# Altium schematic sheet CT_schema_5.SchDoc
size 278 x 236 mm
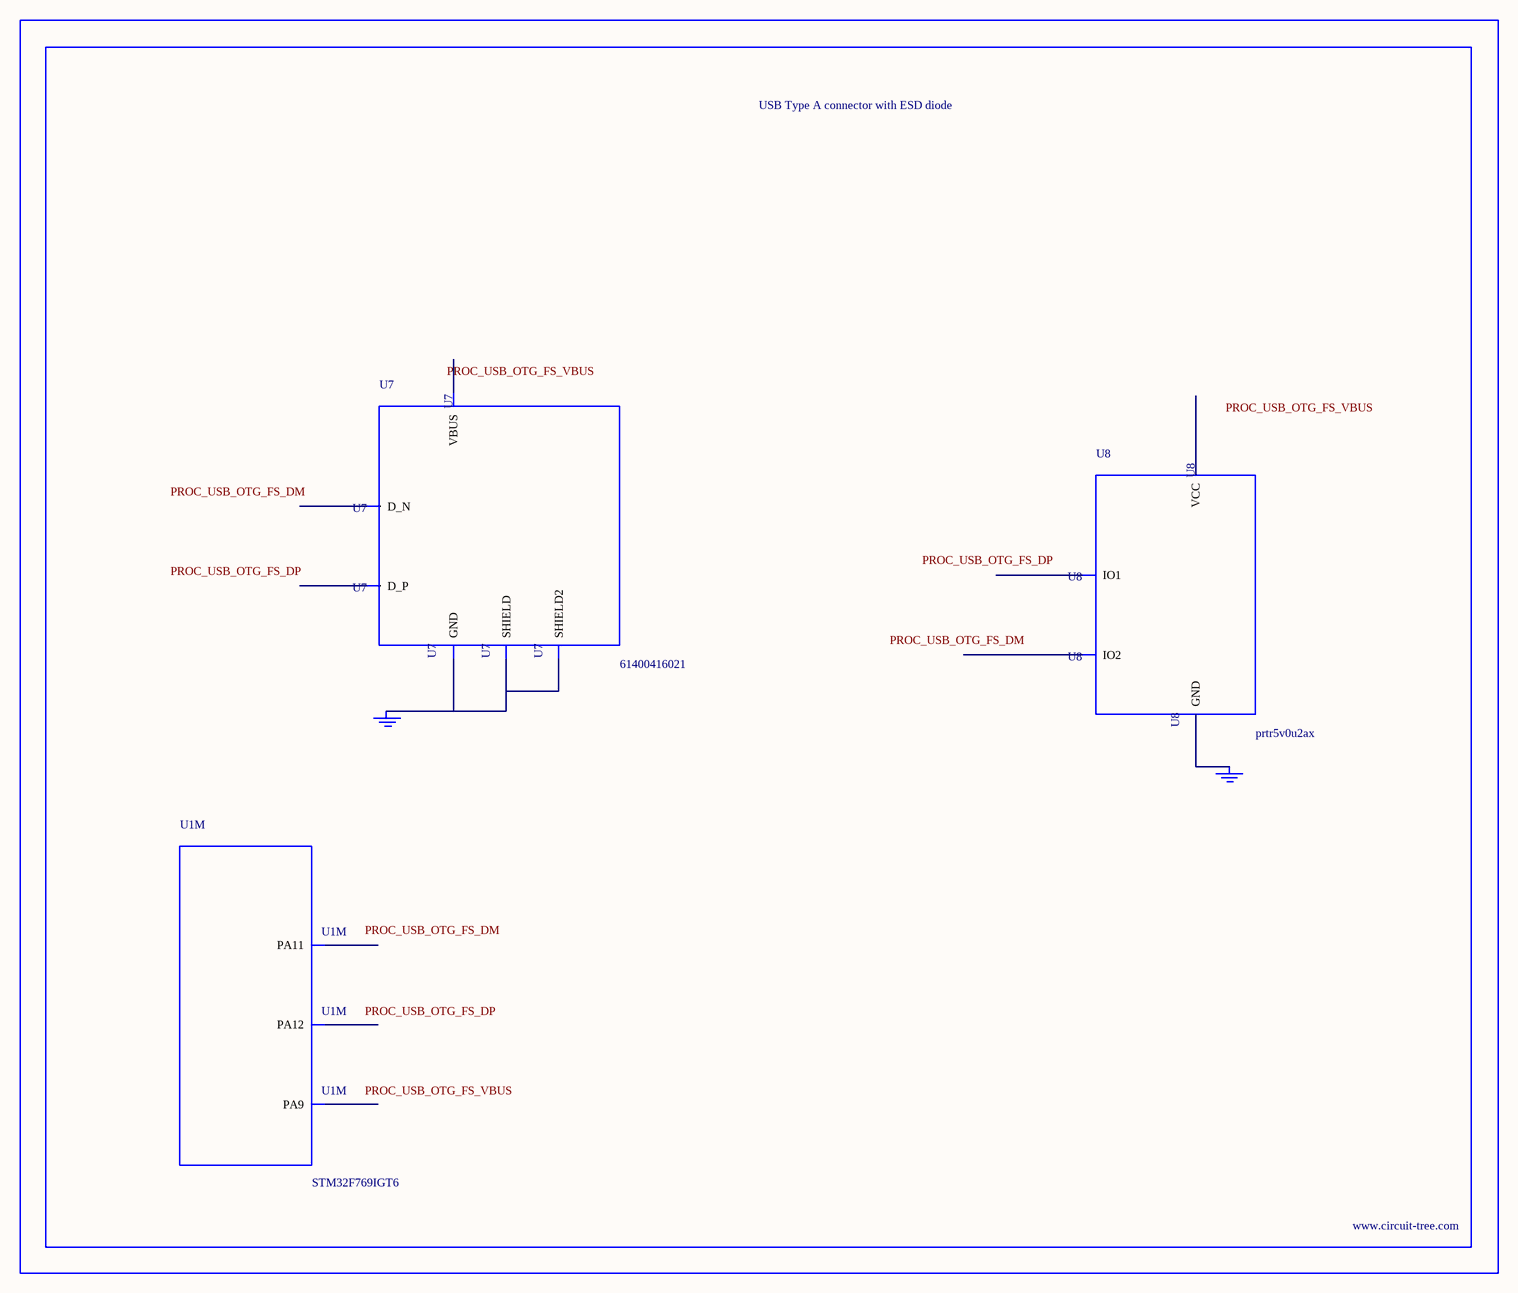
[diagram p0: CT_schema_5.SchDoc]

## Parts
BORDER4  (no value)
GND_INSTANCE_4_0  (no value)
GND_INSTANCE_4_1  (no value)
U1  STM32F769IGT6  [LQFP176]  (part M of 13)
U7  61400416021  [USB-A-H]
U8  prtr5v0u2ax  [SOT143B]

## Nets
NetGND_INSTANCE_4_0_0: GND_INSTANCE_4_0.0(GND) U7.4(GND) U7.5(SHIELD) U7.6(SHIELD2)
NetGND_INSTANCE_4_1_0: GND_INSTANCE_4_1.0(GND) U8.1(GND)

Not connected (* = marked no-connect by the designer): U1 124(PA9) 126(PA11) 127(PA12); U7 1(VBUS) 2(D_N) 3(D_P); U8 2(IO1) 3(IO2) 4(VCC)

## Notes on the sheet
- Labels drawn without touching a wire or pin: PROC_USB_OTG_FS_DM, PROC_USB_OTG_FS_DP, PROC_USB_OTG_FS_VBUS

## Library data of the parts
BORDER4 = BORDER_PAGE4
GND_INSTANCE_4_0 GND_INSTANCE_4_1 = GND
